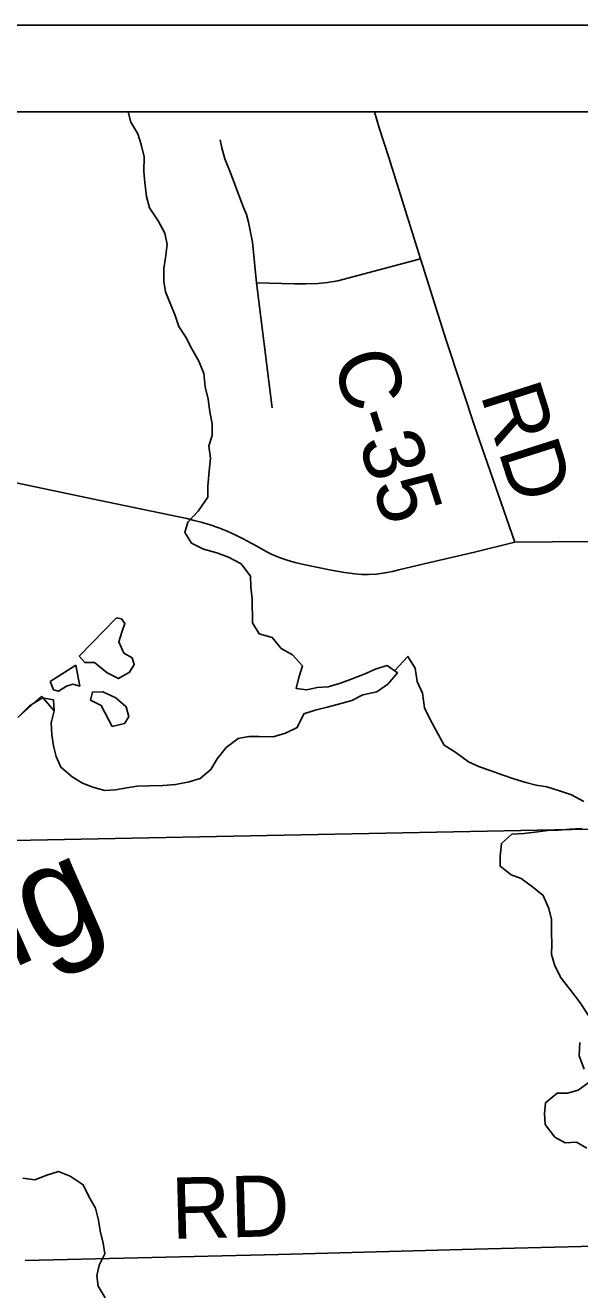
# Model space of a CAD drawing. Extents: x 0 to 34, y 0 to 22.
# Drawn here: x 3.794 to 4.309, y 19.713 to 20.887 of the extents above; entities that cross this region are included whole.
import ezdxf

# ---------------------------------------------------------------- set-up
doc = ezdxf.new("R2010")
doc.units = 0
for name, color, linetype in [('GM_X_Corporation', 7, 'Continuous'), ('GM_X_County_Road', 7, 'Continuous'), ('GM_X_County_Road_Text', 7, 'Continuous'), ('GM_X_Major_Lake', 7, 'Continuous'), ('GM_X_Major_River_Text', 7, 'Continuous'), ('GM_X_Minor_River', 7, 'Continuous'), ('GM_X_Township_Road', 7, 'Continuous'), ('SH_Data', 7, 'Continuous')]:
    doc.layers.add(name, color=color, linetype=linetype)

msp = doc.modelspace()

# ---------------------------------------------------------------- linework, layer by layer
at = {"layer": 'GM_X_Corporation'}
msp.add_lwpolyline([(7.2136, 20.8069), (2.9895, 20.8069), (2.9895, 20.1176), (3.1549, 20.1187), (4.9925, 20.1548), (5.7004, 20.168), (6.0786, 20.1754), (7.2254, 20.198), (7.2157, 20.6753), (7.2146, 20.7526)], close=True, dxfattribs=at)
msp.add_lwpolyline([(7.2872, 17.1772), (7.283, 17.3071), (7.2799, 17.4174), (7.2764, 17.5202), (7.2751, 17.5764), (7.2467, 19.0557), (7.2468, 19.0896), (7.2426, 19.2998), (7.2392, 19.4543), (7.237, 19.6097), (7.2344, 19.7492), (7.2317, 19.8848), (7.2291, 20.0061), (7.2266, 20.122), (7.2254, 20.198), (6.0786, 20.1754), (5.7004, 20.168), (4.9925, 20.1548), (3.1549, 20.1187), (2.9895, 20.1176), (2.9895, 14.989)], dxfattribs=at)
at = {"layer": 'GM_X_County_Road'}
for points in [[(4.2488, 20.4079), (4.2133, 20.5102), (4.185, 20.5951), (4.1612, 20.6705), (4.1317, 20.7646), (4.1229, 20.7922), (4.1185, 20.8069)], [(3.4952, 20.4881), (3.4988, 20.4874), (3.5026, 20.4869), (3.5076, 20.4866), (3.514, 20.4862), (3.5236, 20.4863), (3.5983, 20.487), (3.6493, 20.4874), (3.6549, 20.4872), (3.662, 20.4867), (3.6704, 20.4858), (3.6788, 20.4846), (3.6888, 20.4827), (3.7038, 20.4797), (3.7635, 20.4674), (3.8622, 20.4468)], [(3.8622, 20.4468), (3.9441, 20.4297), (3.951, 20.428), (3.9576, 20.4263), (3.966, 20.4237), (3.9739, 20.4212), (3.9818, 20.418), (3.9897, 20.4143), (3.9973, 20.4104), (4.0041, 20.4067), (4.0058, 20.4058)], [(4.0058, 20.4058), (4.0219, 20.397), (4.0308, 20.3931), (4.0384, 20.3907), (4.0449, 20.3888), (4.0542, 20.3868), (4.0768, 20.3821), (4.0905, 20.3797), (4.1001, 20.3783), (4.1066, 20.3778), (4.1129, 20.3779), (4.1203, 20.3782), (4.1282, 20.3792), (4.1351, 20.3804), (4.1412, 20.3821), (4.1697, 20.3889), (4.2114, 20.3985), (4.2488, 20.4079)], [(4.2488, 20.4079), (4.3882, 20.409), (4.3987, 20.4088), (4.4066, 20.4086), (4.4146, 20.4083), (4.4217, 20.4073), (4.4307, 20.406), (4.4584, 20.4016), (4.6146, 20.3772), (4.8088, 20.346), (4.9883, 20.3188)], [(3.794, 19.7412), (4.0292, 19.747), (4.2114, 19.7519), (4.4586, 19.758)]]:
    msp.add_lwpolyline(points, dxfattribs=at)
at = {"layer": 'GM_X_Major_Lake'}
for points in [[(3.8899, 20.8069), (3.8921, 20.7975), (3.8987, 20.7866), (3.9018, 20.7767), (3.9046, 20.7653), (3.9043, 20.7516), (3.9052, 20.7414), (3.9068, 20.7285), (3.9096, 20.7179), (3.9177, 20.7058), (3.9239, 20.6944), (3.9259, 20.6838), (3.9245, 20.6716), (3.923, 20.6617), (3.9228, 20.6496), (3.9244, 20.6401), (3.9294, 20.6279), (3.9333, 20.6181), (3.9368, 20.6079), (3.9434, 20.598), (3.9488, 20.587), (3.9554, 20.5757), (3.96, 20.5643), (3.9613, 20.5518), (3.9641, 20.5404), (3.9657, 20.5286), (3.9677, 20.5176), (3.9678, 20.5066)], [(3.9678, 20.5066), (3.9648, 20.4971), (3.9661, 20.4857), (3.965, 20.4735), (3.9636, 20.4598), (3.9637, 20.4496), (3.9547, 20.4366), (3.9453, 20.4262), (3.9423, 20.4167), (3.9485, 20.4069), (3.9596, 20.4013), (3.9722, 20.398), (3.9829, 20.3939), (3.9947, 20.3875), (4.0032, 20.3762), (4.0037, 20.3663), (4.0049, 20.3553), (4.0051, 20.3328), (4.0113, 20.3226), (4.0235, 20.3193), (4.0319, 20.3091), (4.0423, 20.3031), (4.0515, 20.2929), (4.0481, 20.2823), (4.0456, 20.272), (4.0555, 20.2709), (4.0653, 20.2729), (4.0756, 20.2734), (4.087, 20.2769), (4.0976, 20.2811), (4.109, 20.2854), (4.12, 20.2901), (4.1302, 20.2932), (4.1398, 20.2864), (4.1307, 20.2761), (4.1205, 20.2688), (4.1076, 20.266), (4.0974, 20.261), (4.0849, 20.2575), (4.0746, 20.2547), (4.0633, 20.252), (4.053, 20.2485), (4.0467, 20.2359), (4.0357, 20.2305), (4.0243, 20.227), (4.0114, 20.2276), (4.0019, 20.2275), (3.992, 20.2256), (3.9807, 20.2171), (3.9724, 20.2068), (3.9664, 20.1968), (3.9566, 20.1884), (3.9463, 20.1853), (3.9338, 20.1829), (3.922, 20.182), (3.9091, 20.1816), (3.8981, 20.1815), (3.8886, 20.1799), (3.8779, 20.1779), (3.868, 20.1774), (3.857, 20.1804), (3.8474, 20.1841), (3.8379, 20.1901), (3.8272, 20.1991), (3.8229, 20.209), (3.8205, 20.2188), (3.8189, 20.2291), (3.8184, 20.2401), (3.821, 20.2512), (3.8205, 20.2614), (3.8102, 20.2632), (3.7981, 20.2559)], [(3.9678, 20.5066), (3.9648, 20.4971), (3.9661, 20.4857), (3.965, 20.4735), (3.9636, 20.4598), (3.9637, 20.4496), (3.9547, 20.4366), (3.9453, 20.4262), (3.9423, 20.4167), (3.9485, 20.4069), (3.9596, 20.4013), (3.9722, 20.398), (3.9829, 20.3939), (3.9947, 20.3875), (4.0032, 20.3762), (4.0037, 20.3663), (4.0049, 20.3553), (4.0051, 20.3328), (4.0113, 20.3226), (4.0235, 20.3193), (4.0319, 20.3091), (4.0423, 20.3031), (4.0515, 20.2929), (4.0481, 20.2823), (4.0456, 20.272), (4.0555, 20.2709), (4.0653, 20.2729), (4.0756, 20.2734), (4.087, 20.2769), (4.0976, 20.2811), (4.109, 20.2854), (4.12, 20.2901), (4.1302, 20.2932), (4.1398, 20.2864), (4.1307, 20.2761), (4.1205, 20.2688), (4.1076, 20.266), (4.0974, 20.261), (4.0849, 20.2575), (4.0746, 20.2547), (4.0633, 20.252), (4.053, 20.2485), (4.0467, 20.2359), (4.0357, 20.2305), (4.0243, 20.227), (4.0114, 20.2276), (4.0019, 20.2275), (3.992, 20.2256), (3.9807, 20.2171), (3.9724, 20.2068), (3.9664, 20.1968), (3.9566, 20.1884), (3.9463, 20.1853), (3.9338, 20.1829), (3.922, 20.182), (3.9091, 20.1816), (3.8981, 20.1815), (3.8886, 20.1799), (3.8779, 20.1779), (3.868, 20.1774), (3.857, 20.1804), (3.8474, 20.1841), (3.8379, 20.1901), (3.8272, 20.1991), (3.8229, 20.209), (3.8205, 20.2188), (3.8189, 20.2291), (3.8184, 20.2401), (3.821, 20.2512), (3.8092, 20.2648)], [(3.8444, 20.302), (3.8494, 20.296), (3.8585, 20.2961), (3.8704, 20.2864), (3.8808, 20.2812), (3.891, 20.287), (3.8954, 20.2943), (3.8935, 20.3003), (3.8858, 20.3048), (3.8811, 20.3154), (3.884, 20.3242), (3.8866, 20.3322), (3.8835, 20.3367), (3.8789, 20.3374)], [(3.8789, 20.3374), (3.8444, 20.302)], [(3.8173, 20.2785), (3.8205, 20.2709), (3.825, 20.2695), (3.8326, 20.2741), (3.8383, 20.2761), (3.8448, 20.2743), (3.8411, 20.2936)], [(3.8411, 20.2936), (3.8173, 20.2785)], [(3.8092, 20.2648), (3.7872, 20.2452)], [(3.8749, 20.2366), (3.8863, 20.2394), (3.8904, 20.2456), (3.888, 20.255), (3.8784, 20.2633), (3.8661, 20.2688), (3.8566, 20.2687), (3.8548, 20.2611), (3.8648, 20.2563)], [(3.7872, 20.2452), (3.7981, 20.2559)], [(3.8648, 20.2563), (3.8749, 20.2366)]]:
    msp.add_lwpolyline(points, dxfattribs=at)
at = {"layer": 'GM_X_Minor_River'}
for points in [[(4.1369, 20.2884), (4.1495, 20.3017), (4.1561, 20.2907), (4.1581, 20.2786), (4.1631, 20.2676), (4.1648, 20.2539), (4.1702, 20.2433), (4.176, 20.2324), (4.183, 20.2195), (4.1941, 20.2127), (4.2056, 20.2041), (4.2159, 20.1992), (4.2258, 20.1959), (4.2369, 20.1918), (4.2479, 20.1881), (4.259, 20.1848), (4.2685, 20.1822), (4.2784, 20.1807), (4.2902, 20.177), (4.3013, 20.1733), (4.3128, 20.167)], [(4.3111, 20.1422), (4.2997, 20.1414), (4.2894, 20.1405), (4.2795, 20.1401), (4.2678, 20.1388), (4.2571, 20.1376), (4.2461, 20.1368), (4.2363, 20.1283), (4.2352, 20.1165), (4.235, 20.107), (4.2453, 20.0991), (4.2548, 20.0958), (4.2652, 20.0879), (4.2751, 20.08), (4.2802, 20.0679), (4.2829, 20.0576), (4.2827, 20.0458), (4.2831, 20.0348), (4.2829, 20.0253), (4.286, 20.0147), (4.2918, 20.0033), (4.2999, 19.9931), (4.3087, 19.9814), (4.3191, 19.9659)], [(4.3091, 19.9434), (4.3084, 19.9313), (4.3131, 19.9188)], [(4.3178, 19.9066), (4.3076, 19.8993), (4.2977, 19.8966), (4.2882, 19.8965), (4.2772, 19.8877), (4.2762, 19.8778), (4.277, 19.8675), (4.2859, 19.8558), (4.2954, 19.8506), (4.3061, 19.851), (4.3157, 19.8454)], [(3.7918, 19.8176), (3.8032, 19.8162), (3.8142, 19.8205), (3.8252, 19.824), (3.8359, 19.8195), (3.8481, 19.8116), (3.8532, 19.8006), (3.8594, 19.7897), (3.8621, 19.7787), (3.8637, 19.7688), (3.8665, 19.7574), (3.8681, 19.7475), (3.8629, 19.7369), (3.8607, 19.727), (3.8619, 19.7175), (3.8685, 19.7065)]]:
    msp.add_lwpolyline(points, dxfattribs=at)
at = {"layer": 'GM_X_Township_Road'}
for points in [[(4.0236, 20.5324), (4.0088, 20.6485), (4.0051, 20.686), (4.0014, 20.7046), (3.9997, 20.7117), (3.9969, 20.7183), (3.984, 20.7521), (3.9795, 20.7635), (3.9767, 20.7736), (3.9752, 20.7809)], [(4.0088, 20.6485), (4.0443, 20.6474), (4.0548, 20.6474), (4.066, 20.6478), (4.0748, 20.6488), (4.0844, 20.6503), (4.1612, 20.6705)]]:
    msp.add_lwpolyline(points, dxfattribs=at)
at = {"layer": 'SH_Data'}
msp.add_line((2.8945, 20.8873), (9.8945, 20.8873), dxfattribs=at)

# ---------------------------------------------------------------- texts
at = {"layer": 'GM_X_County_Road_Text'}
for s, rotation, p in [('C-35', 287.7834, (4.0787, 20.5772)), ('RD', 287.65, (4.2165, 20.5449)), ('RD', 1.4806, (3.9304, 19.7613))]:
    msp.add_text(s, height=0.05682, rotation=rotation, dxfattribs=at).set_placement(p)
at = {"layer": 'GM_X_Major_River_Text'}
msp.add_text('Mahoning', height=0.09473, rotation=23.9275, dxfattribs=at).set_placement((3.3633, 19.8261))

doc.saveas('drawing.dxf')
